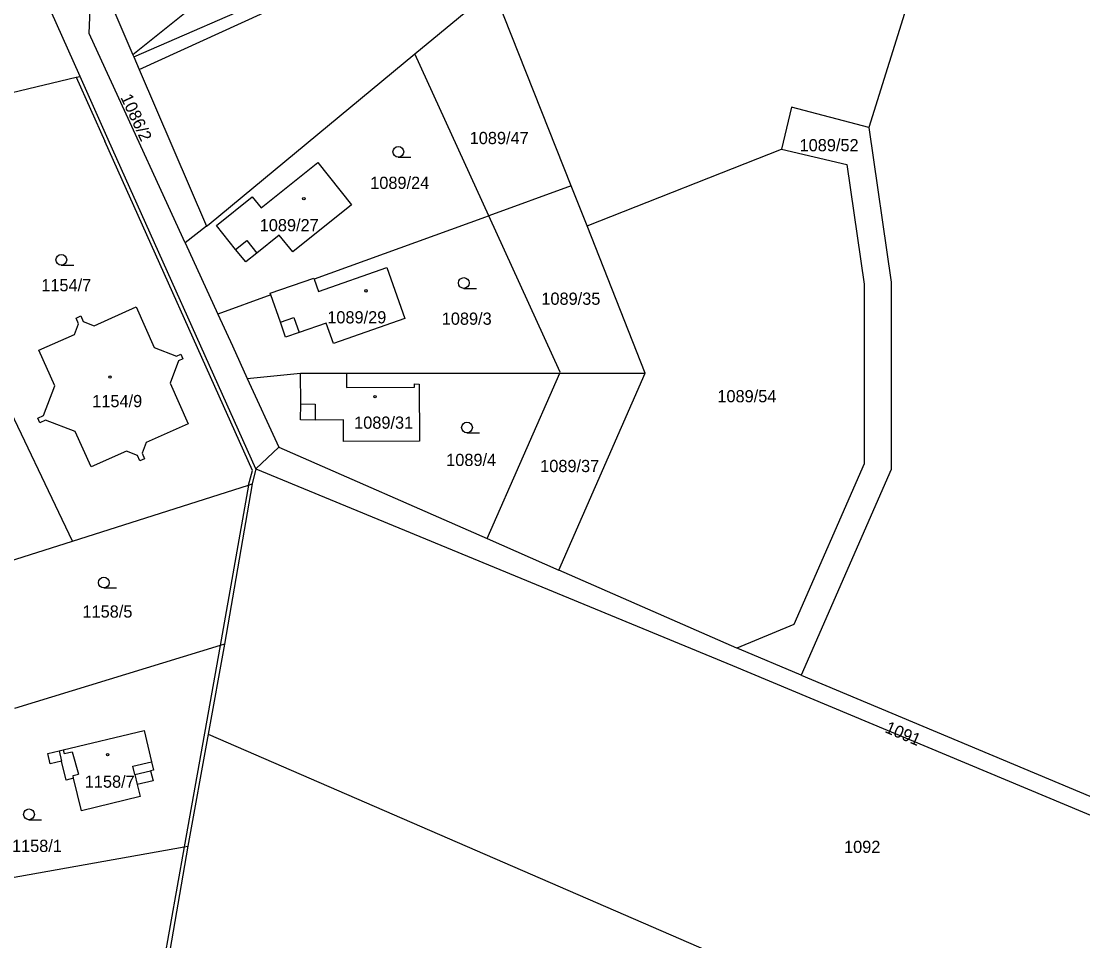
# Model space of a CAD drawing. Extents: x -724107 to -720612, y -1045267 to -1038441.
# Drawn here: x -721994.2 to -721846.3, y -1044219.7 to -1044091.6 of the extents above; entities that cross this region are included whole.
import ezdxf

# ---------------------------------------------------------------- set-up
doc = ezdxf.new("R2010")
doc.units = 0
for name, color, linetype in [('Hranice parcel', 7, 'Continuous'), ('Parcelní čísla', 7, 'Continuous'), ('Vnitřní kresba', 7, 'Continuous'), ('Značky budov', 7, 'Continuous'), ('Značky kultur', 7, 'Continuous')]:
    doc.layers.add(name, color=color, linetype=linetype)

msp = doc.modelspace()

# ---------------------------------------------------------------- linework, layer by layer
at = {"layer": 'Hranice parcel'}
for p, q in [((-721865.34, -1044071.77), (-721876.14, -1044106.37)), ((-721985.93, -1044099.27), (-721994.07, -1044081.11)), ((-721939.37, -1044096.15), (-721928.43, -1044087.1)), ((-721917.58, -1044114.51), (-721928.43, -1044087.1)), ((-721978.63, -1044096.27), (-721978.5, -1044096.56)), ((-721978.5, -1044096.56), (-721977.74, -1044098.33)), ((-721929.06, -1044118.68), (-721939.37, -1044096.15)), ((-721977.74, -1044098.33), (-721968.37, -1044120.11)), ((-721915.37, -1044120.1), (-721888.3, -1044109.39)), ((-721917.58, -1044114.51), (-721929.06, -1044118.68)), ((-721915.37, -1044120.1), (-721917.58, -1044114.51)), ((-721968.37, -1044120.11), (-721971.32, -1044122.45)), ((-721907.26, -1044140.58), (-721915.37, -1044120.1)), ((-721971.32, -1044122.45), (-721966.78, -1044132.37)), ((-721959.4, -1044129.69), (-721966.78, -1044132.37)), ((-721987.04, -1044163.99), (-722000.76, -1044135.22)), ((-721962.68, -1044141.33), (-721955.25, -1044140.6)), ((-721962.68, -1044141.33), (-721958.3, -1044150.89)), ((-721955.25, -1044140.6), (-721948.86, -1044140.59)), ((-721948.86, -1044140.59), (-721919.14, -1044140.58)), ((-721929.26, -1044163.64), (-721919.14, -1044140.58)), ((-721919.28, -1044168.02), (-721907.26, -1044140.58)), ((-721919.14, -1044140.58), (-721907.26, -1044140.58)), ((-721958.3, -1044150.89), (-721961.47, -1044153.93)), ((-721958.3, -1044150.89), (-721929.26, -1044163.64)), ((-721961.47, -1044153.93), (-721961.99, -1044156.03)), ((-721961.99, -1044156.03), (-721965.84, -1044178.33)), ((-721996.83, -1044167.13), (-721987.04, -1044163.99)), ((-721929.26, -1044163.64), (-721919.28, -1044168.02)), ((-721894.49, -1044178.9), (-721919.28, -1044168.02)), ((-721965.84, -1044178.33), (-721968.11, -1044190.86)), ((-721968.11, -1044190.86), (-721970.94, -1044206.48))]:
    msp.add_line(p, q, dxfattribs=at)
for points in [[(-721907.88, -1044039.57), (-721964.23, -1044084.73), (-721978.63, -1044096.27)], [(-721978.5, -1044096.56), (-721958.36, -1044087.75), (-721929.65, -1044067.65), (-721892.32, -1044057.25)], [(-721977.74, -1044098.33), (-721957.68, -1044089.17), (-721928.83, -1044069.15), (-721894.94, -1044059.42)], [(-721971.32, -1044122.45), (-721981.57, -1044100.08), (-721982.41, -1044098.27), (-721984.68, -1044093.31), (-721984.57, -1044089.93), (-721982.26, -1044087.94)], [(-721982.26, -1044087.94), (-721981.42, -1044089.79), (-721978.63, -1044096.27)], [(-721968.37, -1044120.11), (-721968.01, -1044119.83), (-721939.37, -1044096.15)], [(-722012.11, -1044105.49), (-721986.49, -1044099.4), (-721985.93, -1044099.27)], [(-721961.47, -1044153.93), (-721982.04, -1044108.05), (-721985.93, -1044099.27)], [(-721876.14, -1044106.37), (-721886.91, -1044103.55), (-721888.3, -1044109.39)], [(-721876.14, -1044106.37), (-721873.03, -1044127.95), (-721873.03, -1044154.03), (-721885.57, -1044182.65)], [(-721888.3, -1044109.39), (-721879.18, -1044111.55), (-721876.78, -1044128.22), (-721876.78, -1044153.25), (-721886.58, -1044175.62), (-721894.49, -1044178.9)], [(-721966.98, -1044120.03), (-721962.01, -1044116.06), (-721960.77, -1044117.58), (-721952.85, -1044111.28), (-721948.17, -1044117.16), (-721956.36, -1044123.71), (-721958.22, -1044121.39), (-721961.34, -1044123.89), (-721962.9, -1044125.11), (-721964.31, -1044123.39), (-721966.98, -1044120.03)], [(-721929.06, -1044118.68), (-721929.53, -1044118.88), (-721953.38, -1044127.51)], [(-721919.14, -1044140.58), (-721919.09, -1044140.46), (-721929.06, -1044118.68)], [(-721953.38, -1044127.51), (-721952.77, -1044129.23), (-721943.24, -1044125.88), (-721940.74, -1044133.01), (-721950.69, -1044136.46), (-721951.69, -1044133.66), (-721955.46, -1044134.95), (-721957.34, -1044135.57), (-721958.06, -1044133.49), (-721959.4, -1044129.69)], [(-721959.4, -1044129.69), (-721959.48, -1044129.47), (-721953.43, -1044127.35), (-721953.38, -1044127.51)], [(-721971.95, -1044137.96), (-721971.66, -1044138.61), (-721972.25, -1044138.87), (-721973.44, -1044141.98), (-721970.91, -1044147.64), (-721976.75, -1044150.25), (-721977.33, -1044151.76), (-721976.99, -1044152.54), (-721977.63, -1044152.83), (-721977.98, -1044152.05), (-721979.49, -1044151.47), (-721984.42, -1044153.67), (-721986.63, -1044148.74), (-721990.79, -1044147.16), (-721991.56, -1044147.5), (-721991.85, -1044146.86), (-721991.07, -1044146.51), (-721989.48, -1044142.35), (-721991.69, -1044137.42), (-721986.76, -1044135.22), (-721986.18, -1044133.71), (-721986.53, -1044132.93), (-721985.88, -1044132.64), (-721985.54, -1044133.42), (-721984.02, -1044134), (-721978.17, -1044131.38), (-721975.65, -1044137.04), (-721972.54, -1044138.22), (-721971.95, -1044137.96)], [(-721966.78, -1044132.37), (-721964.75, -1044136.81), (-721962.68, -1044141.33)], [(-721948.86, -1044140.59), (-721948.86, -1044142.58), (-721939.38, -1044142.57), (-721939.38, -1044142.11), (-721938.74, -1044142.12), (-721938.68, -1044150.09), (-721949.26, -1044150.13), (-721949.28, -1044147.12), (-721953.23, -1044147.14), (-721955.26, -1044147.12), (-721955.24, -1044144.87), (-721955.25, -1044140.6)], [(-721961.47, -1044153.93), (-721895.13, -1044181.3), (-721805.29, -1044218.87), (-721788.61, -1044220.82)], [(-721987.04, -1044163.99), (-721962.51, -1044156.2), (-721961.99, -1044156.03)], [(-721965.84, -1044178.33), (-721966.48, -1044178.53), (-721995.09, -1044187.32)], [(-721885.57, -1044182.65), (-721894.13, -1044179.06), (-721894.49, -1044178.9)], [(-721885.57, -1044182.65), (-721804.6, -1044216.59), (-721787.91, -1044218.39)], [(-721990.11, -1044195.02), (-721990.46, -1044193.57), (-721988.88, -1044193.19), (-721988.3, -1044193.05), (-721977.05, -1044190.36), (-721976, -1044194.74), (-721975.73, -1044195.89), (-721976.14, -1044195.99), (-721975.8, -1044197.37), (-721978, -1044197.89), (-721977.61, -1044199.55), (-721985.78, -1044201.55), (-721986.86, -1044197.02), (-721987.91, -1044197.27), (-721988.53, -1044194.65), (-721990.11, -1044195.02)], [(-721968.11, -1044190.86), (-721865.19, -1044235.55), (-721799.2, -1044261.03)], [(-722008.2, -1044213.13), (-721971.46, -1044206.57), (-721970.94, -1044206.48)], [(-721970.94, -1044206.48), (-721973.94, -1044223.69), (-721974.07, -1044224.9)]]:
    msp.add_lwpolyline(points, dxfattribs=at)
at = {"layer": 'Vnitřní kresba'}
for p, q in [((-721986.49, -1044099.4), (-721982.54, -1044108.31)), ((-721961.97, -1044154.16), (-721982.54, -1044108.31)), ((-721964.31, -1044123.39), (-721962.76, -1044122.13)), ((-721962.76, -1044122.13), (-721961.34, -1044123.89)), ((-721958.06, -1044133.49), (-721956.19, -1044132.85)), ((-721956.19, -1044132.85), (-721955.46, -1044134.95)), ((-721955.24, -1044144.87), (-721953.24, -1044144.91)), ((-721953.24, -1044144.91), (-721953.23, -1044147.14)), ((-721962.51, -1044156.2), (-721961.97, -1044154.16)), ((-721962.51, -1044156.2), (-721966.48, -1044178.53)), ((-721966.48, -1044178.53), (-721968.65, -1044190.76)), ((-721968.65, -1044190.76), (-721971.46, -1044206.57)), ((-721988.88, -1044193.19), (-721988.53, -1044194.65)), ((-721988.3, -1044193.05), (-721988.17, -1044193.59)), ((-721988.17, -1044193.59), (-721987.09, -1044193.33)), ((-721987.09, -1044193.33), (-721986.17, -1044196.46)), ((-721978.6, -1044195.36), (-721976, -1044194.74)), ((-721978.33, -1044196.51), (-721978.6, -1044195.36)), ((-721978.33, -1044196.51), (-721976.14, -1044195.99)), ((-721986.95, -1044196.64), (-721986.17, -1044196.46)), ((-721986.86, -1044197.02), (-721986.95, -1044196.64)), ((-721978.33, -1044196.51), (-721978, -1044197.89)), ((-721971.46, -1044206.57), (-721974.48, -1044223.59))]:
    msp.add_line(p, q, dxfattribs=at)
at = {"layer": 'Značky budov'}
for centre in [(-721954.81, -1044116.29), (-721946.15, -1044129.14), (-721981.8, -1044141.14), (-721944.89, -1044143.88), (-721982.13, -1044193.74)]:
    msp.add_circle(centre, 0.175, dxfattribs=at)
at = {"layer": 'Značky kultur'}
for p, q in [((-721941.65, -1044110.53), (-721939.9, -1044110.53)), ((-721988.58, -1044125.57), (-721986.83, -1044125.57)), ((-721932.53, -1044128.79), (-721930.78, -1044128.79)), ((-721932.09, -1044148.92), (-721930.34, -1044148.92)), ((-721982.66, -1044170.52), (-721980.91, -1044170.52)), ((-721993.08, -1044202.8), (-721991.33, -1044202.8))]:
    msp.add_line(p, q, dxfattribs=at)
for centre in [(-721941.65, -1044109.78), (-721988.58, -1044124.82), (-721932.53, -1044128.04), (-721932.09, -1044148.17), (-721982.66, -1044169.77), (-721993.08, -1044202.05)]:
    msp.add_circle(centre, 0.75, dxfattribs=at)

# ---------------------------------------------------------------- texts
at = {"layer": 'Parcelní čísla'}
for s, rotation, p in [('1086/2', 295, (-721980.37, -1044102.19)), ('1091', 337, (-721874.01, -1044190.58))]:
    msp.add_text(s, height=1.7, rotation=rotation, dxfattribs=at).set_placement(p)
for s, p in [('1089/47', (-721931.71, -1044108.7)), ('1089/52', (-721885.77, -1044109.7)), ('1089/24', (-721945.56, -1044114.94)), ('1089/27', (-721960.95, -1044120.84)), ('1154/7', (-721991.37, -1044129.2)), ('1089/35', (-721921.73, -1044131.08)), ('1089/29', (-721951.54, -1044133.67)), ('1089/3', (-721935.6, -1044133.86)), ('1089/54', (-721897.22, -1044144.66)), ('1154/9', (-721984.27, -1044145.34)), ('1089/31', (-721947.8, -1044148.34)), ('1089/4', (-721934.98, -1044153.53)), ('1089/37', (-721921.89, -1044154.38)), ('1158/5', (-721985.63, -1044174.65)), ('1158/7', (-721985.31, -1044198.34)), ('1158/1', (-721995.45, -1044207.29)), ('1092', (-721879.58, -1044207.42))]:
    msp.add_text(s, height=1.7, dxfattribs=at).set_placement(p)

doc.saveas('drawing.dxf')
